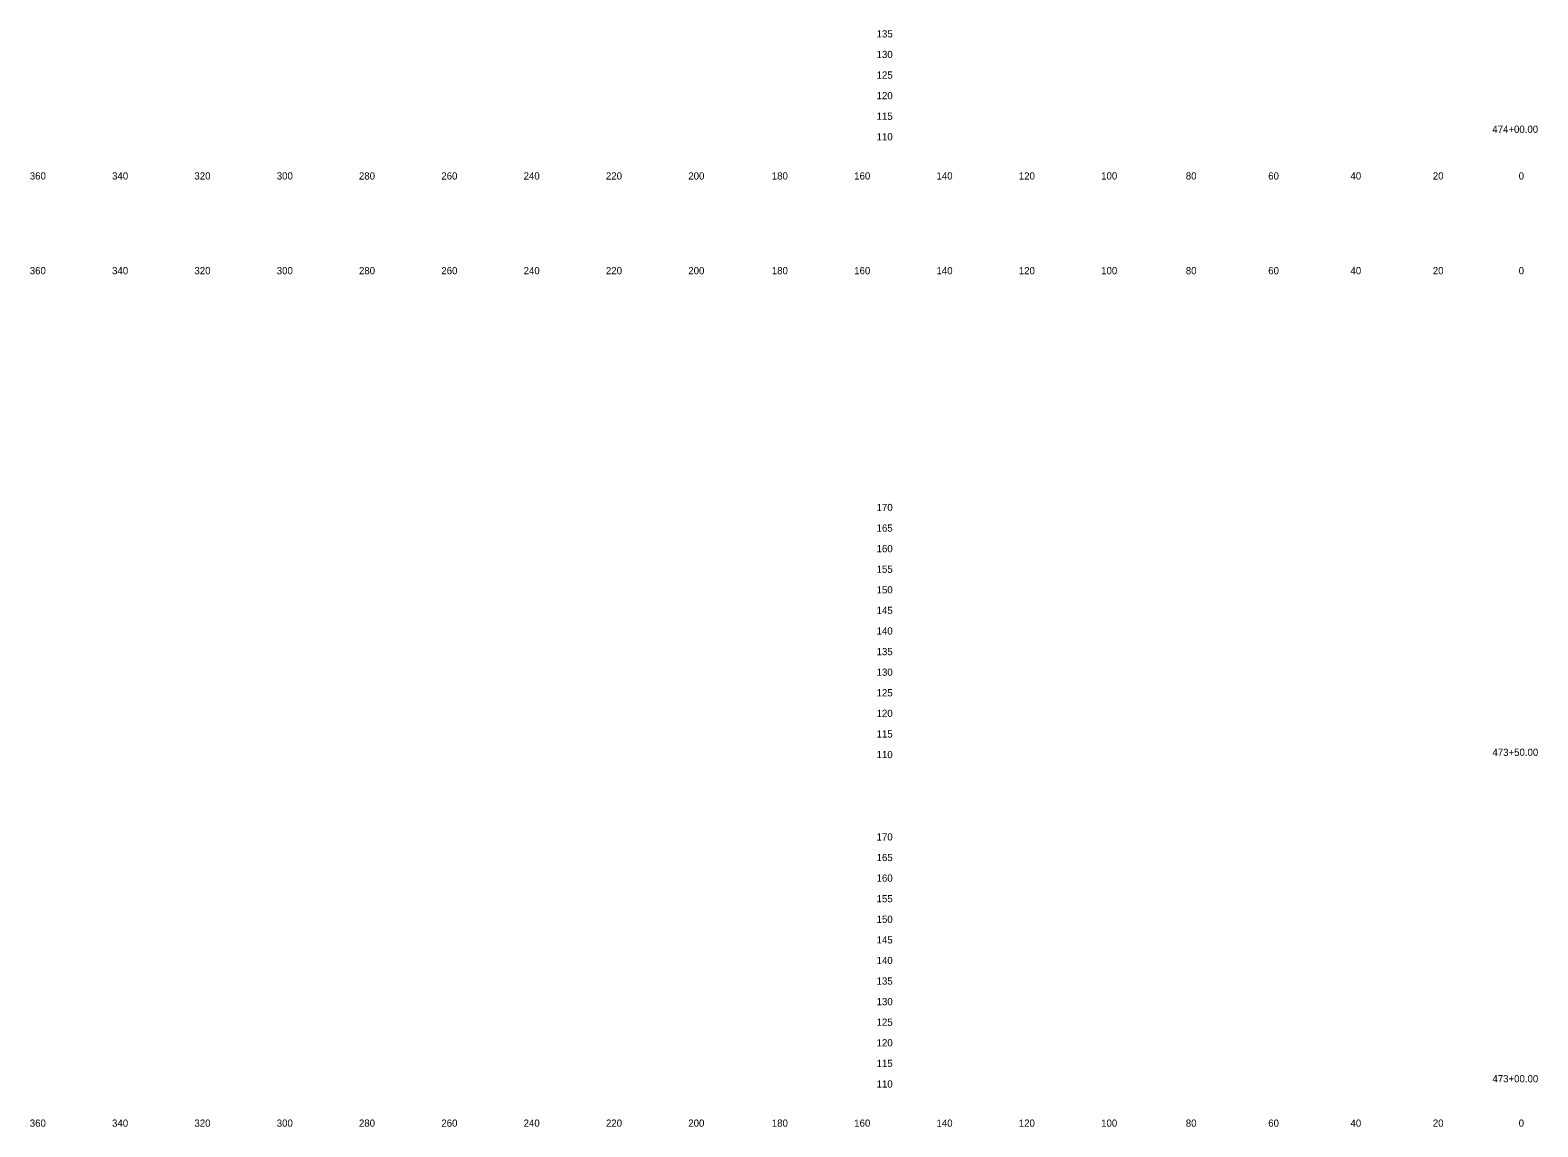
# Model space of a CAD drawing. Extents: x 21281 to 22024, y 6472 to 15198.
# Drawn here: x 21280.5 to 21646.8, y 10845.3 to 11111.6 of the extents above; entities that cross this region are included whole.
import ezdxf

# ---------------------------------------------------------------- set-up
doc = ezdxf.new("R2010")
doc.units = 0
for name, color, linetype in [('Draft_XS_Grid', 7, 'Continuous'), ('Draft_XS_Text', 7, 'Continuous'), ('SLOPE_STAKES_FILL', 7, 'Continuous')]:
    doc.layers.add(name, color=color, linetype=linetype)

msp = doc.modelspace()

# ---------------------------------------------------------------- texts
at = {"layer": 'Draft_XS_Grid'}
for s, p in [('  135  ', (21484.84, 11109.84)), ('  130  ', (21484.84, 11104.84)), ('  125  ', (21484.84, 11099.84)), ('  120  ', (21484.84, 11094.84)), ('  115  ', (21484.84, 11089.84)), ('  110  ', (21484.84, 11084.84)), ('  170  ', (21484.84, 10994.84)), ('  165  ', (21484.84, 10989.84)), ('  160  ', (21484.84, 10984.84)), ('  155  ', (21484.84, 10979.84)), ('  150  ', (21484.84, 10974.84)), ('  145  ', (21484.84, 10969.84)), ('  140  ', (21484.84, 10964.84)), ('  135  ', (21484.84, 10959.84)), ('  130  ', (21484.84, 10954.84)), ('  125  ', (21484.84, 10949.84)), ('  120  ', (21484.84, 10944.84)), ('  115  ', (21484.84, 10939.84)), ('  110  ', (21484.84, 10934.84)), ('  170  ', (21484.84, 10914.84)), ('  165  ', (21484.84, 10909.84)), ('  160  ', (21484.84, 10904.84)), ('  155  ', (21484.84, 10899.84)), ('  150  ', (21484.84, 10894.84)), ('  145  ', (21484.84, 10889.84)), ('  140  ', (21484.84, 10884.84)), ('  135  ', (21484.84, 10879.84)), ('  130  ', (21484.84, 10874.84)), ('  125  ', (21484.84, 10869.84)), ('  120  ', (21484.84, 10864.84)), ('  115  ', (21484.84, 10859.84)), ('  110  ', (21484.84, 10854.84))]:
    msp.add_text(s, height=1.75, dxfattribs=at).set_placement(p)
at = {"layer": 'Draft_XS_Text'}
for s, p in [('  360  ', (21279.14, 11075.34)), ('  340  ', (21299.13, 11075.34)), ('  320  ', (21319.13, 11075.34)), ('  300  ', (21339.13, 11075.34)), ('  280  ', (21359.1, 11075.34)), ('  260  ', (21379.11, 11075.34)), ('  240  ', (21399.1, 11075.34)), ('  220  ', (21419.1, 11075.34)), ('  200  ', (21439.1, 11075.34)), ('  180  ', (21459.39, 11075.34)), ('  160  ', (21479.4, 11075.34)), ('  140  ', (21499.39, 11075.34)), ('  120  ', (21519.39, 11075.34)), ('  100  ', (21539.39, 11075.34)), ('  80  ', (21559.95, 11075.34)), ('  60  ', (21579.97, 11075.34)), ('  40  ', (21599.95, 11075.34)), ('  20  ', (21619.95, 11075.34)), ('  0  ', (21640.81, 11075.34)), ('  0  ', (21640.81, 11075.34)), ('  360  ', (21279.14, 11052.34)), ('  340  ', (21299.13, 11052.34)), ('  320  ', (21319.13, 11052.34)), ('  300  ', (21339.13, 11052.34)), ('  280  ', (21359.1, 11052.34)), ('  260  ', (21379.11, 11052.34)), ('  240  ', (21399.1, 11052.34)), ('  220  ', (21419.1, 11052.34)), ('  200  ', (21439.1, 11052.34)), ('  180  ', (21459.39, 11052.34)), ('  160  ', (21479.4, 11052.34)), ('  140  ', (21499.39, 11052.34)), ('  120  ', (21519.39, 11052.34)), ('  100  ', (21539.39, 11052.34)), ('  80  ', (21559.95, 11052.34)), ('  60  ', (21579.97, 11052.34)), ('  40  ', (21599.95, 11052.34)), ('  20  ', (21619.95, 11052.34)), ('  0  ', (21640.81, 11052.34)), ('  0  ', (21640.81, 11052.34)), ('  360  ', (21279.14, 10845.34)), ('  340  ', (21299.13, 10845.34)), ('  320  ', (21319.13, 10845.34)), ('  300  ', (21339.13, 10845.34)), ('  280  ', (21359.1, 10845.34)), ('  260  ', (21379.11, 10845.34)), ('  240  ', (21399.1, 10845.34)), ('  220  ', (21419.1, 10845.34)), ('  200  ', (21439.1, 10845.34)), ('  180  ', (21459.39, 10845.34)), ('  160  ', (21479.4, 10845.34)), ('  140  ', (21499.39, 10845.34)), ('  120  ', (21519.39, 10845.34)), ('  100  ', (21539.39, 10845.34)), ('  80  ', (21559.95, 10845.34)), ('  60  ', (21579.97, 10845.34)), ('  40  ', (21599.95, 10845.34)), ('  20  ', (21619.95, 10845.34)), ('  0  ', (21640.81, 10845.34)), ('  0  ', (21640.81, 10845.34))]:
    msp.add_text(s, height=1.75, dxfattribs=at).set_placement(p)
at = {"layer": 'SLOPE_STAKES_FILL'}
for s, p in [('  474+00.00  ', (21634.4, 11086.68)), ('  473+50.00  ', (21634.43, 10935.38)), ('  473+00.00  ', (21634.43, 10856.13))]:
    msp.add_text(s, height=1.75, dxfattribs=at).set_placement(p)

doc.saveas('drawing.dxf')
